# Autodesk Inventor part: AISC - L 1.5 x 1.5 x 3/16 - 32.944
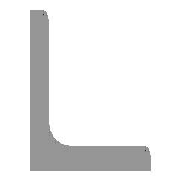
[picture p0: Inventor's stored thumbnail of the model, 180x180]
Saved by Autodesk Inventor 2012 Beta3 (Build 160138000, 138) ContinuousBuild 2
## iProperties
IsCustomPart: 1
Created: 2010-11
Part Number: AISC - L 1.5 x 1.5 x 3/16 - 32.944
Material: Steel, Mild
Description: Angle Steel
Document SubType Name: Modeling
Standard: ANSI
Designer: Beta-8540w
Standards Organization: ANSI
Language: en-US
Size Designation: L 1.5 x 1.5 x 3/16
Categories: <MemberInstance><Categories><Category DisplayName="Structural Shapes" InternalName="089c4875-fa83-4c05-b084-43b9cc11f5ed" Mnemonic="GRDR"><CategoryParameter Dis
Stock Number: L 1.5 x 1.5 x 3/16
Density: 7.86 g/cm^3
G_L: 32.944 in
G_W: 1.500 in
G_H: 1.500 in
_CCFamilyMember: 5
_CCFamilyDisplayName: ANSI L (Equal angles) - Angle Steel
_FrameMemberDoc: Frame Member File
_Version: 15.0.0
_GetPNFromCC: 1
Author: Beta-8540w
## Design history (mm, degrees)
node "Start plane"
node "End plane"
sketch "Sketch"
  geometry: L1 (38.1, 0)-(0, 0); L2 (0, 0)-(0, 38.1); L3 (0, 38.1)-(2.476, 38.1); L4 (4.762, 35.814)-(4.762, 9.589); L5 (9.588, 4.763)-(35.814, 4.763); L6 (38.1, 2.477)-(38.1, 0); L7 (0, -11.041)-(0, 31.538); L8 (-11.041, 0)-(31.538, 0); L9 (0, 48.496)-(0, -20.964) reference; L10 (-20.964, 0)-(48.496, 0) reference; A1 r 4.826 centre (9.588, 9.589) between (4.762, 9.589) and (9.588, 4.763); A2 r 2.286 centre (2.476, 35.814) between (4.762, 35.814) and (2.476, 38.1); A3 r 2.286 centre (35.814, 2.477) between (38.1, 2.477) and (35.814, 4.763); 3 further points
  constraints: 16 end point, 6 point on circle, 6 point on line, 6 tangent, 4 parallel, 3 centre point, 2 collinear, 1 equal radius, 1 horizontal, 1 perpendicular
  dimensions: "d0" = 38.1 distance between parallel lines of L6 L2 (= G_H); "d1" = 38.1 distance between parallel lines of L3 L1 (= G_H); "d2" = 4.7625 distance between parallel lines of L2 L4 (= G_T); "d3" = 4.7625 distance between parallel lines of L1 L5 (= G_T); "d10" = 0 distance between parallel lines of L7 L2 (computed from ex); "d11" = 0 distance between parallel lines of L8 L1 (computed from d10); "d14" = 4.826 radius of A1 (= G_IR); "d15" = 2.286 radius of A2 (= G_ER)
extrude "Body" new body sketch "Sketch" stored distance "d4" = 836.76542 (= G_L); taper "d5" = 0 deg
node "Driven Length"
  sketch "Sketch3"
    geometry: L1 (0, 0)-(10, 0) reference
    constraints: 2 end point, 1 horizontal
  workplane "Work Plane3"
  sketch "Sketch4"
    geometry: L1 (-2, 0)-(12, 0) reference; L2 (-2, 836.765)-(12, 836.765) reference
    dimensions: "d17" = 836.76542 distance between parallel lines of L1 L2 (derived)
body "Solid1"
other parameters: "G_H" = 38.1 [user parameter; used in 2 equation terms], "G_T" = 4.7625 [user parameter; used in 2 equation terms], "G_ER" = 2.286 [user parameter; used in 1 equation term], "G_IR" = 4.826 [user parameter; used in 1 equation term], "G_L" = 836.76542 (= d17) [user parameter; used in 1 equation term], "ex" = 0 [user parameter; used in 1 equation term], "G_OFFSET_START" = 0 [user parameter; used in 1 equation term], "G_OFFSET_END" = 0 [user parameter; used in 1 equation term], "d12" = 0 (computed from G_OFFSET_START), "d13" = 836.76542 (= G_OFFSET_END + B_L), "B_L" = 836.76542 [user parameter; used in 1 equation term], "d16" = 90 deg, "MAS" = 0.26787 [user parameter]
